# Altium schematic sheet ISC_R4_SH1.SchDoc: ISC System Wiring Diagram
size B; DrawnBy: Filiberto Clara; Engineer: Filiberto Clara; Organization: LIGO Laboratory; Address1: California Institute of Technology; Address2: Massachusetts Institute of Technology; SheetNumber: 15; SheetTotal: 37
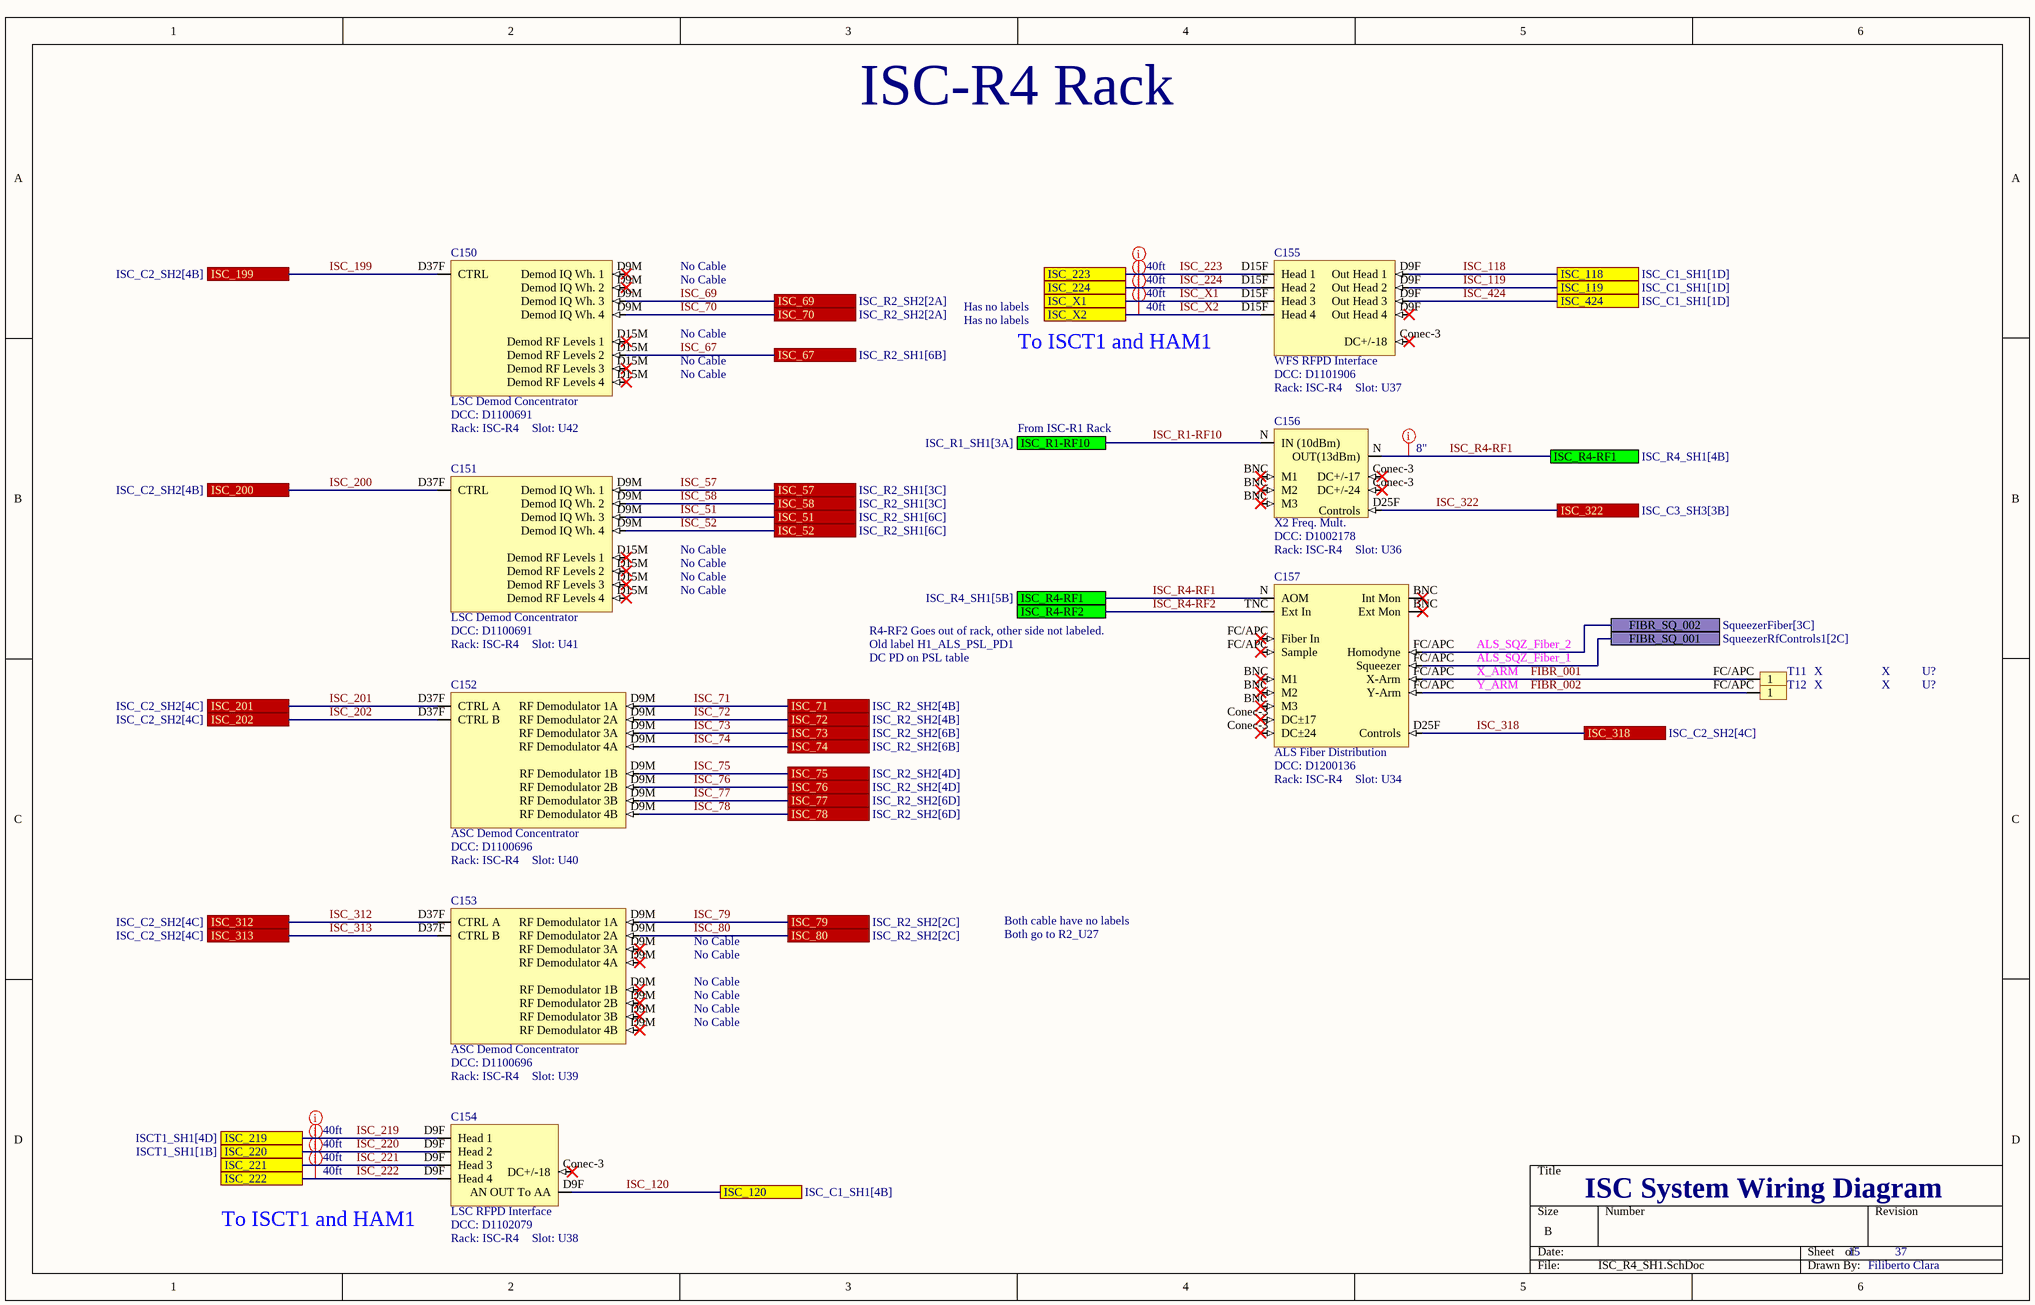
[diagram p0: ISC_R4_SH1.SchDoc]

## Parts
C150  LSC Demod Concentrator  DCC: D1100691  Rack: ISC-R4  Slot: U42
C151  LSC Demod Concentrator  DCC: D1100691  Rack: ISC-R4  Slot: U41
C152  ASC Demod Concentrator  DCC: D1100696  Rack: ISC-R4  Slot: U40
C153  ASC Demod Concentrator  DCC: D1100696  Rack: ISC-R4  Slot: U39
C154  LSC RFPD Interface  DCC: D1102079  Rack: ISC-R4  Slot: U38
C155  WFS RFPD Interface  DCC: D1101906  Rack: ISC-R4  Slot: U37
C156  X2 Freq. Mult.  DCC: D1002178  Rack: ISC-R4  Slot: U36
C157  ALS Fiber Distribution  DCC: D1200136  Rack: ISC-R4  Slot: U34
T11  X  Slot: U?
T12  X  Slot: U?

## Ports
FIBR_SQ_001 (see SqueezerRfControls1[2C]), FIBR_SQ_002 (see SqueezerFiber[3C]), ISC_51 (see ISC_R2_SH1[6C]), ISC_52 (see ISC_R2_SH1[6C]), ISC_57 (see ISC_R2_SH1[3C]), ISC_58 (see ISC_R2_SH1[3C]), ISC_67 (see ISC_R2_SH1[6B]), ISC_69 (see ISC_R2_SH2[2A]), ISC_70 (see ISC_R2_SH2[2A]), ISC_71 (see ISC_R2_SH2[4B]), ISC_72 (see ISC_R2_SH2[4B]), ISC_73 (see ISC_R2_SH2[6B]), ISC_74 (see ISC_R2_SH2[6B]), ISC_75 (see ISC_R2_SH2[4D]), ISC_76 (see ISC_R2_SH2[4D]), ISC_77 (see ISC_R2_SH2[6D]), ISC_78 (see ISC_R2_SH2[6D]), ISC_79 (see ISC_R2_SH2[2C]), ISC_80 (see ISC_R2_SH2[2C]), ISC_118 (see ISC_C1_SH1[1D]), ISC_119 (see ISC_C1_SH1[1D]), ISC_120 (see ISC_C1_SH1[4B]), ISC_199 (see ISC_C2_SH2[4B]), ISC_200 (see ISC_C2_SH2[4B]), ISC_201 (see ISC_C2_SH2[4C]), ISC_202 (see ISC_C2_SH2[4C]), ISC_219 (see ISCT1_SH1[4D]), ISC_220 (see ISCT1_SH1[1B]), ISC_221, ISC_222, ISC_223, ISC_224, ISC_312 (see ISC_C2_SH2[4C]), ISC_313 (see ISC_C2_SH2[4C]), ISC_318 (see ISC_C2_SH2[4C]), ISC_322 (see ISC_C3_SH3[3B]), ISC_424 (see ISC_C1_SH1[1D]), ISC_R1-RF10 (see ISC_R1_SH1[3A]), ISC_R4-RF1 (see ISC_R4_SH1[4B]), ISC_R4-RF1 (see ISC_R4_SH1[5B]), ISC_R4-RF2, ISC_X1, ISC_X2

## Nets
FIBR_001: C157.FC/APC(Fiber_In) T11.FC/APC(1)
FIBR_002: C157.FC/APC(Y-Arm) T12.FC/APC(1)
FIBR_SQ_001: C157.FC/APC(Squeezer) ; port FIBR_SQ_001
FIBR_SQ_002: C157.FC/APC(Homodyne) ; port FIBR_SQ_002
ISC_51: C151.D9M(Demod_IQ_Wh._3) ; port ISC_51
ISC_52: C151.D9M(Demod_IQ_Wh._4) ; port ISC_52
ISC_57: C151.D9M(Demod_IQ_Wh._1) ; port ISC_57
ISC_58: C151.D9M(Demod_IQ_Wh._2) ; port ISC_58
ISC_67: C150.D15M(Demod_RF_Levels_1) ; port ISC_67
ISC_69: C150.D9M(Demod_IQ_Wh._1) ; port ISC_69
ISC_70: C150.D9M(Demod_IQ_Wh._4) ; port ISC_70
ISC_71: C152.D9M(RF_Demodulator_1A) ; port ISC_71
ISC_72: C152.D9M(RF_Demodulator_2A) ; port ISC_72
ISC_73: C152.D9M(RF_Demodulator_3A) ; port ISC_73
ISC_74: C152.D9M(RF_Demodulator_4A) ; port ISC_74
ISC_75: C152.D9M(RF_Demodulator_1B) ; port ISC_75
ISC_76: C152.D9M(RF_Demodulator_2B) ; port ISC_76
ISC_77: C152.D9M(RF_Demodulator_3B) ; port ISC_77
ISC_78: C152.D9M(RF_Demodulator_4B) ; port ISC_78
ISC_79: C153.D9M(RF_Demodulator_1A) ; port ISC_79
ISC_80: C153.D9M(RF_Demodulator_2A) ; port ISC_80
ISC_118: C155.D9F(Out_Head_1) ; port ISC_118
ISC_119: C155.D9F(Out_Head_2) ; port ISC_119
ISC_120: C154.D9F(AN_OUT_To_AA) ; port ISC_120
ISC_199: C150.D37F(CTRL) ; port ISC_199
ISC_200: C151.D37F(CTRL) ; port ISC_200
ISC_201: C152.D37F(CTRL_A) ; port ISC_201
ISC_202: C152.D37F(CTRL_B) ; port ISC_202
ISC_219: C154.D9F(Head_1) ; port ISC_219
ISC_220: C154.D9F(Head_2) ; port ISC_220
ISC_221: C154.D9F(Head_3) ; port ISC_221
ISC_222: C154.D9F(Head_4) ; port ISC_222
ISC_223: C155.D15F(Head_1) ; port ISC_223
ISC_224: C155.D15F(Head_2) ; port ISC_224
ISC_312: C153.D37F(CTRL_A) ; port ISC_312
ISC_313: C153.D37F(CTRL_B) ; port ISC_313
ISC_318: C157.D25F(Controls) ; port ISC_318
ISC_322: C156.D25F(Controls) ; port ISC_322
ISC_424: C155.D9F(Out_Head_3) ; port ISC_424
ISC_R1-RF10: C156.N(IN_(10dBm)) ; port ISC_R1-RF10
ISC_R4-RF1: C156.N(OUT(13dBm)) C157.N(AOM) ; port ISC_R4-RF1
ISC_R4-RF2: C157.TNC(Ext_In) ; port ISC_R4-RF2
ISC_X1: C155.D15F(Head_3) ; port ISC_X1
ISC_X2: C155.D15F(Head_4) ; port ISC_X2

Not connected (* = marked no-connect by the designer): C151 D15M(Demod_RF_Levels_1)*; C154 Conec-3(DC+/-18)*; C155 Conec-3(DC+/-18)*; C156 BNC(M1)* Conec-3(DC+/-17)*; C157 BNC(Int_Mon)* Conec-3(DC±17)*

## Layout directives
Length: 40ft: ISC_219, ISC_220, ISC_221, ISC_222, ISC_223, ISC_224, ISC_X1, ISC_X2
Length: 8": ISC_R4-RF1

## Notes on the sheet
- ISC-R4 Rack
- No Cable
- Has no labels
- To ISCT1 and HAM1
- From ISC-R1 Rack
- R4-RF2 Goes out of rack, other side not labeled.
- Old label H1_ALS_PSL_PD1
- ALS_SQZ_Fiber_2
- DC PD on PSL table
- ALS_SQZ_Fiber_1
- X_ARM
- Y_ARM
- Both cable have no labels
- Both go to R2_U27
- (near C154) To ISCT1 and HAM1

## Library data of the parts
C150 C151 = LSC Demod Concentrator: Serial: Sxxxxxxx; System: ISC
C152 C153 = ASC Demod Concentrator: Serial: Sxxxxxxx; System: ISC
C154 = LSC RFPD Interface: Serial: Sxxxxxxx; System: ISC
C155 = WFS RFPD Interface: Serial: Sxxxxxxx; System: ISC
C156 = X2 Freq. Mult.: Serial: Sxxxxxxx; System: ISC
C157 = ALS Fiber Distribution_V6: Serial: Sxxxxxxx; System: ISC
T11 = Placeholder: Place Holder; Serial: Sxxxxxxx; System: ISC; DCC: tbd
T12 = Placeholder: Serial: Sxxxxxxx; System: ISC; DCC: tbd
